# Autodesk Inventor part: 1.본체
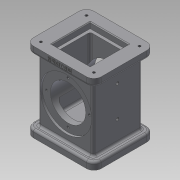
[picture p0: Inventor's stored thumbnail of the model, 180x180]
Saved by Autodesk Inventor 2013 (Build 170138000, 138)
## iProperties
Created: 2017-08
Part Number: 1.본체
Material: 일반
Document SubType Name: Modeling
Designer: cad14
Density: 1 g/cm^3
Author: cad14
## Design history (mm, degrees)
sketch "스케치1"
  geometry: L1 (-46, -41)-(46, -41); L2 (46, -41)-(46, 41); L3 (46, 41)-(-46, 41); L4 (-46, 41)-(-46, -41); L5 (-46, -41)-(46, 41); L6 (46, -41)-(-46, 41); 1 further point
  constraints: 12 end point, 2 midpoint, 2 parallel, 1 horizontal, 1 perpendicular
  dimensions: "d0" = 92 distance between parallel lines of L2 L4; "d2" = 82 distance between parallel lines of L3 L1
extrude "돌출1" new body sketch "스케치1" distance "d3" = 10; taper "d4" = 0 deg
sketch "스케치2"
  geometry: L1 (-37, -33)-(37, -33); L2 (37, -33)-(37, 33); L3 (37, 33)-(-37, 33); L4 (-37, 33)-(-37, -33); L5 (-37, -33)-(37, 33); L6 (37, -33)-(-37, 33); 1 further point
  constraints: 12 end point, 2 midpoint, 2 parallel, 1 horizontal, 1 perpendicular
  dimensions: "d5" = 74 distance between parallel lines of L2 L4; "d7" = 66 distance between parallel lines of L3 L1
extrude "돌출2" join sketch "스케치2" distance "d8" = 88; taper "d9" = 0 deg
sketch "스케치3"
  geometry: L1 (-46, -41)-(46, -41); L2 (46, -41)-(46, 41); L3 (46, 41)-(-46, 41); L4 (-46, 41)-(-46, -41); L5 (-46, -41)-(46, 41); L6 (46, -41)-(-46, 41); 1 further point
  constraints: 12 end point, 2 midpoint, 2 parallel, 1 horizontal, 1 perpendicular
  dimensions: "d10" = 92 distance between parallel lines of L2 L4; "d12" = 82 distance between parallel lines of L3 L1
extrude "돌출3" join sketch "스케치3" distance "d13" = 10; taper "d14" = 0 deg
sketch "스케치4"
  geometry: L1 (-22, -22)-(22, -22); L2 (22, -22)-(22, 22); L3 (22, 22)-(-22, 22); L4 (-22, 22)-(-22, -22); L5 (-22, -22)-(22, 22); L6 (22, -22)-(-22, 22); 1 further point
  constraints: 12 end point, 2 midpoint, 2 parallel, 1 horizontal, 1 perpendicular
  dimensions: "d15" = 44 distance between parallel lines of L2 L4; "d17" = 44 distance between parallel lines of L1 L3
extrude "돌출4" cut sketch "스케치4" distance "d18" = 82; taper "d19" = 0 deg
sketch "스케치5"
  geometry: L1 (22, 22)-(22, -22) reference; L2 (22, -22)-(-22, -22) reference; L3 (-22, -22)-(-22, 22) reference; L4 (-22, 22)-(22, 22) reference; L5 (-26, -26)-(26, -26); L6 (26, -26)-(26, 26); L7 (26, 26)-(-26, 26); L8 (-26, 26)-(-26, -26); L9 (-26, -26)-(26, 26); L10 (26, -26)-(-26, 26); 1 further point
  constraints: 12 end point, 2 midpoint, 2 parallel, 1 horizontal, 1 perpendicular
  dimensions: "d20" = 52 distance between parallel lines of L6 L8; "d22" = 52 distance between parallel lines of L7 L5
extrude "돌출5" cut sketch "스케치5" distance "d23" = 8; taper "d24" = 0 deg
sketch "스케치6"
  geometry: L1 (-9, -10)-(83, -10) reference; C1 r 24 at (37, 44); 2 further points
  constraints: 1 centre point, 1 midpoint, 1 vertical alignment
  dimensions: "d25" = 54 distance from line of C1.centre L1; "d26" = 48 diameter of C1
extrude "돌출6" cut sketch "스케치6" stored distance "d27" = 8; taper "d28" = 0 deg
sketch "스케치7"
  geometry: C1 r 24 at (37, 44) reference; C2 r 35 at (37, 44); 1 further point
  constraints: 1 centre point
  dimensions: "d29" = 70 diameter of C2
extrude "돌출7" cut sketch "스케치7" distance "d31" = 3; taper "d32" = 0 deg
sketch "스케치8"
  geometry: L1 (-24, -24)-(24, -24); L2 (24, -24)-(24, 24); L3 (24, 24)-(-24, 24); L4 (-24, 24)-(-24, -24); L5 (-24, -24)-(24, 24); L6 (24, -24)-(-24, 24); 1 further point
  constraints: 12 end point, 2 midpoint, 2 parallel, 1 horizontal, 1 perpendicular
  dimensions: "d33" = 48 distance between parallel lines of L2 L4; "d35" = 48 distance between parallel lines of L3 L1
extrude "돌출8" cut sketch "스케치8" distance "d36" = 16; taper "d37" = 0 deg
sketch "스케치9"
  geometry: C1 r 24 at (0, 0) reference; 2 further points
  constraints: 1 vertical alignment
  dimensions: "d38" = 29 distance of point (0, 29) C1.centre
hole "구멍1" sketch "스케치9" at (0, 29) diameter "d39" = 3.242; stored, may be unused: countersink angle "d43" = 90 deg, drill point angle "d45" = 118 deg; dims "d40" = 4, "d41" = 4, "d42" = 2, "d44" = 6
sketch "스케치10"
  geometry: L1 (10, -8)-(10, 74) reference; 5 further points
  constraints: 2 horizontal alignment, 2 midpoint
  dimensions: "d49" = 38 distance from line of point (-28, 33) L1; "d50" = 42 distance of point (-70, 33) point (-28, 33)
hole "구멍2" sketch "스케치10" at (-28, 33), (-70, 33) diameter "d51" = 4.134; stored, may be unused: countersink angle "d55" = 90 deg, drill point angle "d57" = 118 deg; dims "d52" = 4, "d53" = 4, "d54" = 2, "d56" = 20
fillet "모깎기1" dims "d58" = 10
fillet "모깎기2" dims "d59" = 3
fillet "모깎기3" dims "d60" = 3
fillet "모깎기5" dims "d62" = 3
fillet "모깎기6" dims "d63" = 3
sketch "스케치11"
  geometry: A1 r 10 centre (-36, 31) between (-36, 41) and (-46, 31) reference; A2 r 10 centre (-36, -31) between (-46, -31) and (-36, -41) reference; A3 r 10 centre (36, -31) between (36, -41) and (46, -31) reference; A4 r 10 centre (36, 31) between (46, 31) and (36, 41) reference; 1 further point
hole "구멍3" sketch "스케치11" at (-36, 31), (36, 31), (36, -31), (-36, -31) diameter "d64" = 3.242; stored, may be unused: countersink angle "d68" = 90 deg, drill point angle "d70" = 118 deg; dims "d65" = 4, "d66" = 4, "d67" = 2, "d69" = 6
sketch "스케치12"
  geometry: A1 r 10 centre (36, 31) between (46, 31) and (36, 41) reference; A2 r 10 centre (-36, 31) between (-36, 41) and (-46, 31) reference; A3 r 10 centre (-36, -31) between (-46, -31) and (-36, -41) reference; A4 r 10 centre (36, -31) between (36, -41) and (46, -31) reference; 1 further point
hole "구멍4" sketch "스케치12" at (-36, 31), (-36, -31), (36, -31), (36, 31) diameter "d71" = 3.242; stored, may be unused: countersink angle "d75" = 90 deg, drill point angle "d77" = 118 deg; dims "d72" = 4, "d73" = 4, "d74" = 2, "d76" = 6
fillet "모깎기7" dims "d78" = 3
fillet "모깎기8" dims "d79" = 3
fillet "모깎기9" dims "d80" = 3
node "작업 평면2"
sketch "스케치14"
  geometry: L1 (-10, 0)-(-10, -7) reference; L2 (0, 0)-(72, 0) reference; 2 further points
  constraints: 1 other
  dimensions: "d87" = 46 distance from line of point (36, -4) L1; "d88" = 4 distance from line of point (36, -4) L2
feature "엠보싱2" sketch "스케치14" dims "d0" = 92, "d2" = 82, "d89" = 0.5, "d90" = 0
chamfer "모따기1" distance "d91" = 1; stored, may be unused: second distance "d92" = 2, angle "d93" = 45 deg
node "솔리드1"
mirror "대칭1"
pattern_circular "원형 패턴1" dims angle "d47" = 360 deg
mirror "대칭2"
